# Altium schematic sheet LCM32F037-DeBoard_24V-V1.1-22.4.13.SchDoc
size A3; SheetNumber: 1; SheetTotal: 1
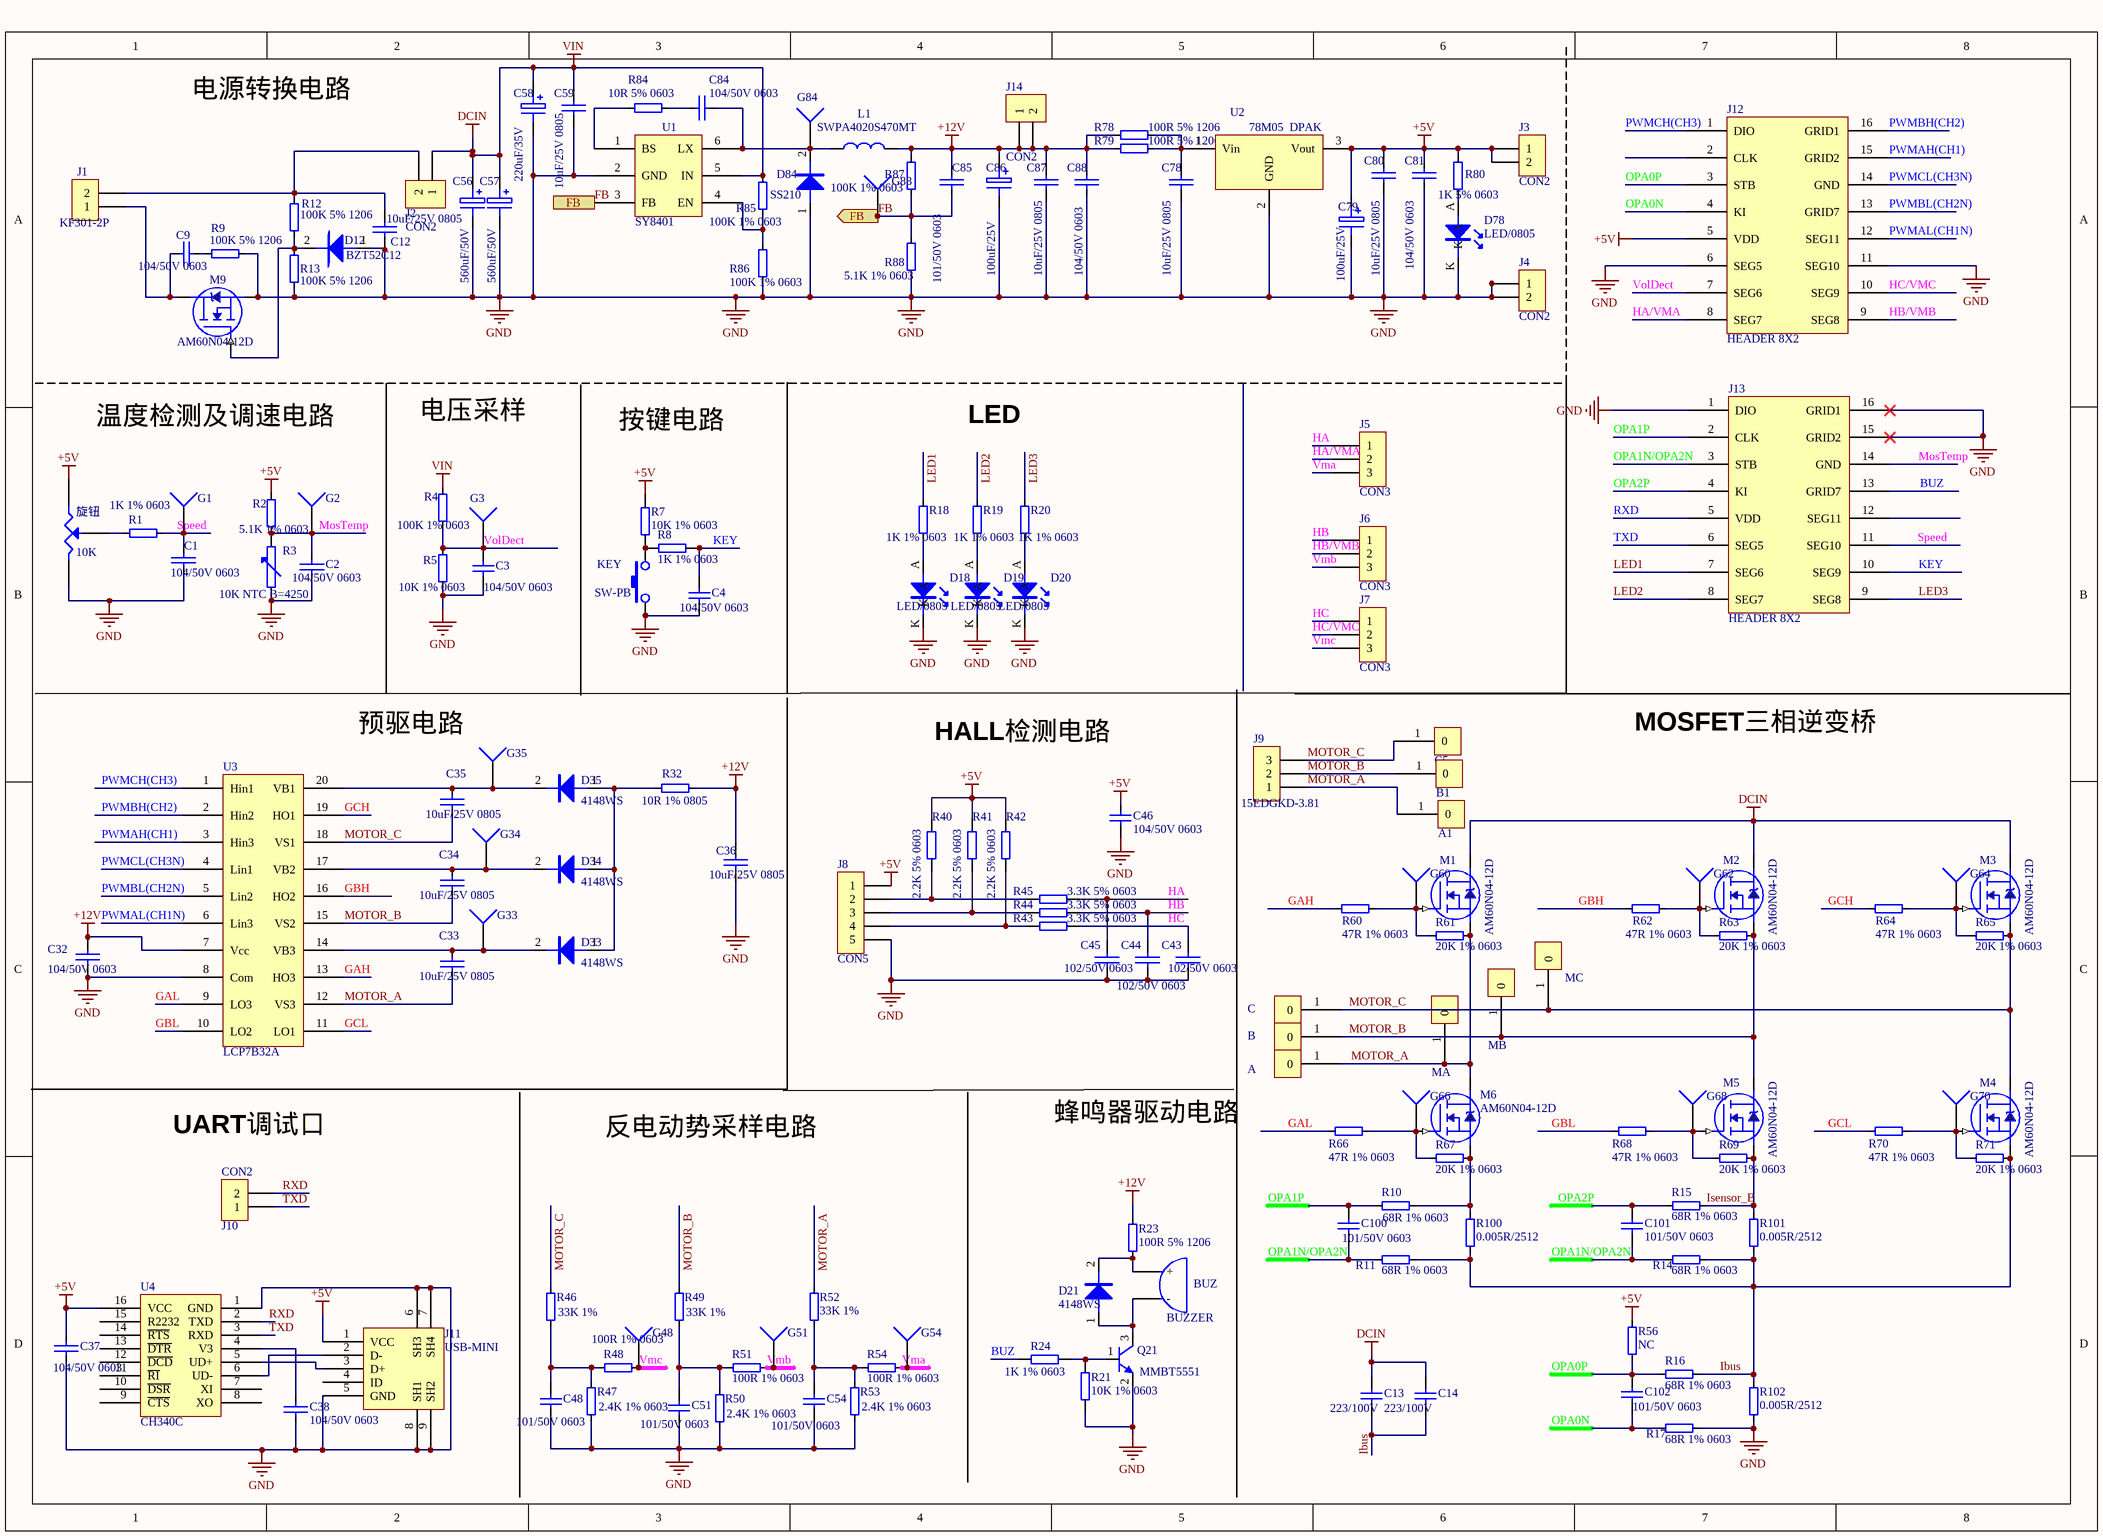
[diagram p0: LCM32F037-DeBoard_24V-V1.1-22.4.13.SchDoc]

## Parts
A  Wire#-(Color)cm  [CON1-D1]  (value not drawn)
A1  Wire#-(Color)cm  [WIRE#18-BK7CM]  (value not drawn)
B  Wire#-(Color)cm  [CON1-D1]  (value not drawn)
B1  Wire#-(Color)cm  [WIRE#18-BK7CM]  (value not drawn)
BUZ  BUZZER  [BELL]
C  Wire#-(Color)cm  [CON1-D1]  (value not drawn)
C1  104/50V 0603  [0603C]
C2  104/50V 0603  [0603C]
C3  104/50V 0603  [0603C]
C4  104/50V 0603  [0603C]
C5  Wire#-(Color)cm  [WIRE#18-BK7CM]  (value not drawn)
C9  104/50V 0603  [0603C]
C12  10uF/25V 0805  [0805C]
C13  223/100V  [CAP-TH_L7.2-W4.0-P5.00-D0.5]
C14  223/100V  [CAP-TH_L7.2-W4.0-P5.00-D0.5]
C32  104/50V 0603  [0603C]
C33  10uF/25V 0805  [0805C]
C34  10uF/25V 0805  [0805C]
C35  10uF/25V 0805  [0805C]
C36  10uF/25V 0805  [0805C]
C37  104/50V 0603  [0603C]
C38  104/50V 0603  [0603C]
C43  102/50V 0603  [0603C]
C44  102/50V 0603  [0603C]
C45  102/50V 0603  [0603C]
C46  104/50V 0603  [0603C]
C48  101/50V 0603  [0603C]
C51  101/50V 0603  [0603C]
C54  101/50V 0603  [0603C]
C56  560uF/50V  [CAP-TH_BD10.0-P5.00-D1.0-FD]
C57  560uF/50V  [CAP-TH_BD10.0-P5.00-D1.0-FD]
C58  220uF/35V  [CAP-TH_BD6.3-P2.50-D0.5-FD]
C59  10uF/25V 0805  [0805C]
C78  10uF/25V 0805  [0805C]
C79  100uF/25V  [EC5]
C80  10uF/25V 0805  [0805C]
C81  104/50V 0603  [0603C]
C84  104/50V 0603  [0603C]
C85  101/50V 0603  [0603C]
C86  100uF/25V  [EC5]
C87  10uF/25V 0805  [0805C]
C88  104/50V 0603  [0603C]
C100  101/50V 0603  [0603C]
C101  101/50V 0603  [0603C]
C102  101/50V 0603  [0603C]
D12  BZT52C12  [SOD-123]
D18  LED/0805  [0805/LED]
D19  LED/0805  [0805/LED]
D20  LED/0805  [0805/LED]
D21  4148WS  [SOD323]
D33  4148WS  [SOD323]
D34  4148WS  [SOD323]
D35  4148WS  [SOD323]
D78  LED/0805  [0805/LED]
D84  SS210  [SMB]
G1  (no value)  [GG]
G2  (no value)  [GG]
G3  (no value)  [GG]
G33  (no value)  [GG]
G34  (no value)  [GG]
G35  (no value)  [GG]
G48  (no value)  [GG]
G51  (no value)  [GG]
G54  (no value)  [GG]
G60  (no value)  [GG]
G62  (no value)  [GG]
G64  (no value)  [GG]
G66  (no value)  [GG]
G68  (no value)  [GG]
G70  (no value)  [GG]
G84  (no value)  [GG]
G88  (no value)  [GG]
J1  KF301-2P  [HB9500SS-9.5]
J2  CON2  [J-DG128-2]
J3  CON2  [SIP2]
J4  CON2  [SIP2]
J5  CON3  [H2.54-1X3]
J6  CON3  [H2.54-1X3]
J7  CON3  [H2.54-1X3]
J8  CON5  [15EDGKD-3.81]
J9  15EDGKD-3.81  [LS243-5.0]
J10  CON2  [H2.54-1X2]
J11  USB-MINI  [MINI-USB-TH_KH-MINI-DIP90-5P-CU - duplicate1]
J12  HEADER 8X2  [DIP16-2]
J13  HEADER 8X2  [DIP16-2]
J14  CON2  [SIP2]
KEY  SW-PB  [SP-SMT6*6*5]
L1  SWPA4020S470MT  [L4532]
M1  AM60N04-12D  [DPAK]
M2  AM60N04-12D  [DPAK]
M3  AM60N04-12D  [DPAK]
M4  AM60N04-12D  [DPAK]
M5  AM60N04-12D  [DPAK]
M6  AM60N04-12D  [DPAK]
M9  AM60N04-12D  [DPAK]
MA  Wire#-(Color)cm  [WIRE#18-BK7CM]  (value not drawn)
MB  Wire#-(Color)cm  [WIRE#18-BK7CM]  (value not drawn)
MC  Wire#-(Color)cm  [WIRE#18-BK7CM]  (value not drawn)
Q21  MMBT5551  [SOT-23A]
R1  1K 1% 0603  [0603R]
R2  5.1K 1% 0603  [0603R]
R3  10K NTC B=4250  [0603R]
R4  100K 1% 0603  [0603R]
R5  10K 1% 0603  [0603R]
R7  10K 1% 0603  [0603R]
R8  1K 1% 0603  [0603R]
R9  100K 5% 1206  [1206R]
R10  68R 1% 0603  [0603R]
R11  68R 1% 0603  [0603R]
R12  100K 5% 1206  [1206R]
R13  100K 5% 1206  [1206R]
R14  68R 1% 0603  [0603R]
R15  68R 1% 0603  [0603R]
R16  68R 1% 0603  [0603R]
R17  68R 1% 0603  [0603R]
R18  1K 1% 0603  [0603R]
R19  1K 1% 0603  [0603R]
R20  1K 1% 0603  [0603R]
R21  10K 1% 0603  [0603R]
R23  100R 5% 1206  [1206R]
R24  1K 1% 0603  [0603R]
R32  10R 1% 0805  [R-0805]
R40  2.2K 5% 0603  [0603R]
R41  2.2K 5% 0603  [0603R]
R42  2.2K 5% 0603  [0603R]
R43  3.3K 5% 0603  [0603R]
R44  3.3K 5% 0603  [0603R]
R45  3.3K 5% 0603  [0603R]
R46  33K 1%  [0603R]
R47  2.4K 1% 0603  [0603R]
R48  100R 1% 0603  [0603R]
R49  33K 1%  [0603R]
R50  2.4K 1% 0603  [0603R]
R51  100R 1% 0603  [0603R]
R52  33K 1%  [0603R]
R53  2.4K 1% 0603  [0603R]
R54  100R 1% 0603  [0603R]
R56  NC  [0603R]
R60  47R 1% 0603  [0603R]
R61  20K 1% 0603  [0603R]
R62  47R 1% 0603  [0603R]
R63  20K 1% 0603  [0603R]
R64  47R 1% 0603  [0603R]
R65  20K 1% 0603  [0603R]
R66  47R 1% 0603  [0603R]
R67  20K 1% 0603  [0603R]
R68  47R 1% 0603  [0603R]
R69  20K 1% 0603  [0603R]
R70  47R 1% 0603  [0603R]
R71  20K 1% 0603  [0603R]
R78  100R 5% 1206  [1206R]
R79  100R 5% 1206  [1206R]
R80  1K 5% 0603  [0603R]
R84  10R 5% 0603  [0603R]
R85  100K 1% 0603  [0603R]
R86  100K 1% 0603  [0603R]
R87  100K 1% 0603  [0603R]
R88  5.1K 1% 0603  [0603R]
R100  0.005R/2512  [2512S]
R101  0.005R/2512  [2512S]
R102  0.005R/2512  [2512S]
U1  SY8401  [SOT-23-6]
U2  78M05  DPAK  [DPAK]
U3  LCP7B32A  [TSSOP-20]
U4  CH340C  [SO-16]
旋钮  10K  [RES-TH_RK09D1110C0R]

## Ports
FB (in), FB (out)

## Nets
+5V: C37.2 C46.1 C79.1 C80.2 C81.1 J3.1 J3.2 J8.1 J11.1(VCC) J12.5(VDD) R2.1 R7.2 R40.2 R41.2 R42.2 R56.2 R80.1 U2.3(Vout) U4.16(VCC) 旋钮.3
+12V: C32.2 C36.2 C85.1 C86.1 C87.2 C88.1 J14.1 J14.2 L1.2 R23.1 R32.2 R78.2 R79.2 R87.1 U3.7(Vcc)
DCIN: C13.1 C14.1 C56.1 C57.1 C58.1 C59.2 J2.1 M1.2(DRAIN) M2.2(DRAIN) M3.2(DRAIN) R4.2 R85.2 U1.5(IN)  [also labelled VIN]
GND: C1.2 C2.2 C3.1 C4.1 C12.1 C32.1 C36.1 C37.1 C38.2 C43.1 C44.1 C45.1 C46.2 C48.1 C51.1 C54.1 C56.2 C57.2 C58.2 C59.1 C78.1 C79.2 C80.1 C81.2 C86.2 C87.1 C88.2 D12.1(A) D18.K D19.K D20.K D78.K D84.1(A) J4.1 J4.2 J8.5 J11.5(GND) J11.6(SH3) J11.7(SH4) J11.8(SH1) J11.9(SH2) J12.6(SEG5) J12.11(SEG10) J13.1(DIO) J13.15(GRID2) J13.16(GRID1) KEY.1 M9.3(SOURCE) Q21.2(E) R3.1 R5.1 R9.2 R13.2 R17.2 R21.1 R47.1 R50.1 R53.1 R86.1 R88.2 R102.2 U1.2(GND) U2.2(GND) U3.8(Com) U4.1(GND) 旋钮.1
BUZ: J13.13(GRID7) R24.1
FB: C85.2 G88.1 R87.2 R88.1 U1.3(FB) ; port FB
GAH: R60.2 U3.13(HO3)
GAL: R66.2 U3.9(LO3)
GBH: R62.2 U3.16(HO2)
GBL: R68.2 U3.10(LO2)
GCH: R64.2 U3.19(HO1)
GCL: R70.2 U3.11(LO1)
HA: C45.2 J5.1 R45.2
HA/VMA: J5.2 J12.8(SEG7)
HB: C44.2 J6.1 R44.2
HB/VMB: J6.2 J12.9(SEG8)
HC: C43.2 J7.1 R43.2
HC/VMC: J7.2 J12.10(SEG9)
Ibus: C13.2 C14.2 M4.3(SOURCE) R11.2 R14.2 R16.2 R71.1 R100.1 R101.1 R102.1
Isensor_B: M5.3(SOURCE) R15.2 R69.1 R101.2
KEY: C4.2 J13.10(SEG9) R8.2
LED1: J13.7(SEG6) R18.2
LED2: J13.8(SEG7) R19.2
LED3: J13.9(SEG8) R20.2
MosTemp: C2.1 G2.1 J13.14(GND) R2.2 R3.2
MOTOR_A: A.1(0) A1.1(0) C33.2 J9.1 M1.3(SOURCE) M6.2(DRAIN) MA.1(0) R52.1 R61.1 U3.12(VS3)
MOTOR_B: B.1(0) B1.1(0) C34.2 J9.2 M2.3(SOURCE) M5.2(DRAIN) MB.1(0) R49.1 R63.1 U3.15(VS2)
MOTOR_C: C.1(0) C5.1(0) C35.2 J9.3 M3.3(SOURCE) M4.2(DRAIN) MC.1(0) R46.1 R65.1 U3.18(VS1)
OPA0N: C102.2 J12.4(KI) R17.1
OPA0P: C102.1 J12.3(STB) R16.1 R56.1
OPA1N/OPA2N: C100.2 C101.2 J13.3(STB) R11.1 R14.1
OPA1P: C100.1 J13.2(CLK) R10.1
OPA2P: C101.1 J13.4(KI) R15.1
PWMAH(CH1): J12.15(GRID2) U3.3(Hin3)
PWMAL(CH1N): J12.12(SEG11) U3.6(Lin3)
PWMBH(CH2): J12.16(GRID1) U3.2(Hin2)
PWMBL(CH2N): J12.13(GRID7) U3.5(Lin2)
PWMCH(CH3): J12.1(DIO) U3.1(Hin1)
PWMCL(CH3N): J12.14(GND) U3.4(Lin1)
RXD: J10.2 J13.5(VDD) U4.2(TXD)
Speed: C1.1 G1.1 J13.11(SEG10) R1.2
TXD: J10.1 J13.6(SEG5) U4.3(RXD)
Vma: G54.1 J5.3 R54.2
Vmb: G51.1 J6.3 R51.2
Vmc: G48.1 J7.3 R48.1
VolDect: C3.2 G3.1 J12.7(SEG6) R4.1 R5.2
NetBUZ_1: BUZ.1(+) D21.2(K) R23.2
NetBUZ_2: BUZ.2(-) D21.1(A) Q21.3(C)
NetC9_1: C9.1 R9.1
NetC9_2: C9.2 J1.1 M9.2(DRAIN)
NetC12_2: C12.2 J1.2 J2.2 R12.1
NetC33_1: C33.1 D33.2(K) G33.1 U3.14(VB3)
NetC34_1: C34.1 D34.2(K) G34.1 U3.17(VB2)
NetC35_1: C35.1 D35.2(K) G35.1 U3.20(VB1)
NetC38_1: C38.1 U4.4(V3)
NetC48_2: C48.2 R46.2 R47.2 R48.2
NetC51_2: C51.2 R49.2 R50.2 R51.1
NetC54_2: C54.2 R52.2 R53.2 R54.1
NetC78_2: C78.2 R78.1 R79.1 U2.1(Vin)
NetC84_1: C84.1 D84.2(K) G84.1 L1.1 U1.6(LX)
NetC84_2: C84.2 R84.1
NetD12_2: D12.2(K) M9.1(GATE) R12.2 R13.1
NetD18_A: D18.A R18.1
NetD19_A: D19.A R19.1
NetD20_A: D20.A R20.1
NetD33_1: D33.1(A) D34.1(A) D35.1(A) R32.1
NetD78_A: D78.A R80.2
NetG60_1: G60.1 M1.1(GATE) R60.1 R61.2
NetG62_1: G62.1 M2.1(GATE) R62.1 R63.2
NetG64_1: G64.1 M3.1(GATE) R64.1 R65.2
NetG66_1: G66.1 M6.1(GATE) R66.1 R67.2
NetG68_1: G68.1 M5.1(GATE) R68.1 R69.2
NetG70_1: G70.1 M4.1(GATE) R70.1 R71.2
NetJ8_2: J8.2 R40.1 R45.1
NetJ8_3: J8.3 R41.1 R44.1
NetJ8_4: J8.4 R42.1 R43.1
NetJ11_2: J11.2(D-) U4.6(UD-)
NetJ11_3: J11.3(D+) U4.5(UD+)
NetKEY_2: KEY.2 R7.1 R8.1
NetM6_3: M6.3(SOURCE) R10.2 R67.1 R100.2
NetQ21_1: Q21.1(B) R21.2 R24.2
NetR1_1: R1.1 旋钮.2
NetR84_2: R84.2 U1.1(BS)
NetR85_1: R85.1 R86.2 U1.4(EN)

Not connected (* = marked no-connect by the designer): J11 4(ID); J12 2(CLK); J13 12(SEG11); U4 7(XI) 8(XO) 9(~{CTS}) 10(~{DSR}) 11(~{RI}) 12(~{DCD}) 13(~{DTR}) 14(~{RTS}) 15(R2232)

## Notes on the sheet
- 电源转换电路
- 温度检测及调速电路
- 电压采样
- 按键电路
- LED
- 预驱电路
- HALL检测电路
- MOSFET三相逆变桥
- UART调试口
- 反电动势采样电路
- 蜂鸣器驱动电路

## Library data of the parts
A A1 B B1 C C5 MA MB MC = Wire
BUZ = BUZZER: 无源蜂鸣器-磁电
C1 C2 C9 C33-C35 C37 C38 C81 C84 C85 C88 C102 = CAP
C3 C12 C32 C36 C43-C45 C48 C51 C54 C59 C78 C80 C87 = CAP: Capacitor
C4 C13 C14 C46 = CAP: Capacitor; Value: 103/50V
C56 C57 C79 C86 = ELE CAP: Electrolytic Capacitor
C58 = ELECTRO1: Electrolytic Capacitor
C100 C101 = CAP: Capacitor; Value: 104/50V
D12 = DIODE_2: SBD
D18-D20 D78 = LED
D21 D33-D35 D84 = DIODE: SBD
G1-G3 G33-G35 G48 G51 G54 G60 G62 G64 G66 G68 G70 G84 G88 = Socket: Plug
J1-J4 J10 J14 = CON2: Connector
J8 = CON5: Connector
J9 = CON3
J12 J13 = TM1617
L1 = INDUCTOR1
M1-M6 M9 = MOSFEN: Low Charge N-Channel MOSFET
Q21 = NPN: NPN General Purpose Amplifier
R1 R2 R4 R5 R7-R21 R23 R24 R32 R40-R54 R56 R60-R71 R78-R80 R84-R88 R100-R102 = RES
R3 = RES-V
U2 = VOLTREG
U3 = So-20CK5G14
U4 = CH340G
旋钮 = POT1: Potentiometer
